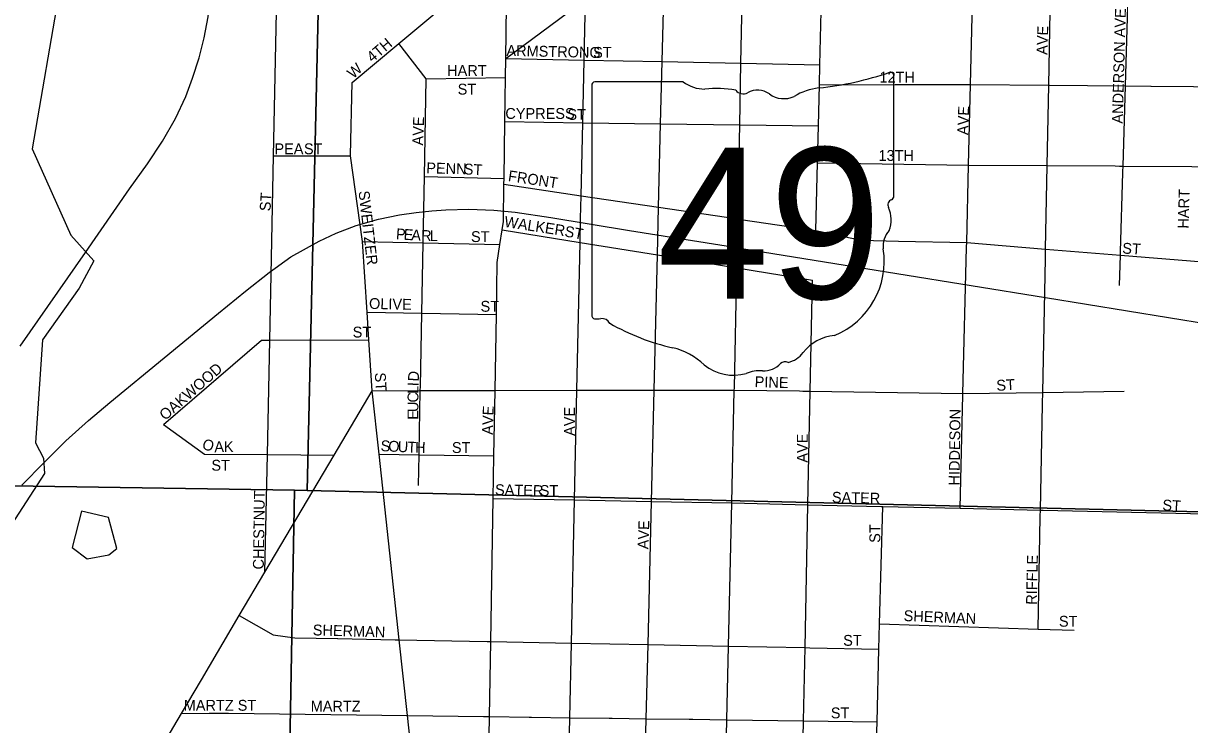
# Model space of a CAD drawing. Extents: x -784 to 1375, y -225 to 440.
# Drawn here: x 287.9 to 308.9, y 339.88 to 352.51 of the extents above; entities that cross this region are included whole.
import ezdxf

# ---------------------------------------------------------------- set-up
doc = ezdxf.new("R2010")
doc.units = 0
for name, color, linetype in [('GM_X_City_Street', 7, 'Continuous'), ('GM_X_City_Street_Text', 7, 'Continuous'), ('GM_X_Minor_Lake', 7, 'Continuous'), ('GM_X_Minor_River', 7, 'Continuous'), ('GM_X_Rail_Line', 7, 'Continuous'), ('GM_X_Section', 7, 'Continuous'), ('GM_X_State_Location', 7, 'Continuous'), ('GM_X_State_Route', 7, 'Continuous'), ('GM_X_State_Shield', 7, 'Continuous'), ('GM_X_Township_Subdivision', 7, 'Continuous'), ('GM_X_Township_Subdivision_Text', 7, 'Continuous')]:
    doc.layers.add(name, color=color, linetype=linetype)

msp = doc.modelspace()

# ---------------------------------------------------------------- linework, layer by layer
at = {"layer": 'GM_X_City_Street'}
for points in [[(293.82, 351.442), (294.658, 352.146), (295.198, 352.598), (296.496, 353.687), (296.611, 353.783), (297.844, 354.818), (299.354, 356.01)], [(296.585, 351.875), (298.02, 352.944), (298.138, 353.027), (298.835, 353.583), (299.456, 354.078), (300.303, 354.834)], [(292.36, 347.981), (292.36, 347.982), (292.404, 350.122), (292.463, 353.002), (292.49, 354.328)], [(298.958, 333.384), (298.958, 333.385), (298.963, 333.583), (299.009, 335.502), (299.057, 337.477), (299.117, 339.989), (299.149, 341.322), (299.211, 343.901), (299.26, 345.904), (299.318, 348.338), (299.339, 349.198), (299.375, 350.7), (299.402, 351.82), (299.43, 352.976), (299.456, 354.078)], [(302.172, 348.778), (302.201, 349.994), (302.217, 350.66), (302.235, 351.404), (302.244, 351.764), (302.273, 352.97), (302.3, 354.083)], [(304.886, 348.487), (304.887, 348.56), (304.922, 349.957), (304.958, 351.406), (304.994, 352.879), (305.035, 354.013)], [(307.7, 349.84), (307.703, 349.939), (307.745, 351.382), (307.788, 352.818), (307.797, 353.948)], [(296.184, 333.611), (296.218, 335.587), (296.251, 337.52), (296.294, 340.026), (296.317, 341.377), (296.361, 343.955), (296.374, 344.723), (296.394, 345.899), (296.418, 347.269), (296.434, 348.201), (296.482, 348.524), (296.522, 348.791), (296.545, 348.943), (296.554, 349.611), (296.556, 349.714), (296.569, 350.739), (296.58, 351.531), (296.585, 351.875), (296.611, 353.783)], [(297.934, 348.991), (297.934, 348.992), (297.943, 349.405), (297.972, 350.719), (297.996, 351.848), (298.02, 352.944)], [(306.305, 348.315), (306.307, 348.444), (306.337, 349.948), (306.365, 351.394), (306.391, 352.724), (306.392, 352.79)], [(295.048, 345.971), (295.074, 347.293), (295.098, 348.554), (295.121, 349.749), (295.155, 351.512), (294.658, 352.146)], [(296.585, 351.875), (297.996, 351.848), (299.402, 351.82), (300.822, 351.792), (302.244, 351.764)], [(294.182, 345.894), (294.122, 346.812), (294.09, 347.31), (294.007, 348.578), (293.792, 350.121), (293.79, 350.135), (293.82, 351.442)], [(295.155, 351.512), (296.58, 351.531)], [(302.235, 351.404), (303.597, 351.405), (303.597, 351.405)], [(303.597, 351.405), (304.958, 351.406), (306.365, 351.394), (306.379, 351.394)], [(306.379, 351.394), (306.38, 351.394), (307.745, 351.382), (308.205, 351.378)], [(308.205, 351.378), (308.208, 351.378), (308.973, 351.371), (310.245, 351.361), (311.377, 351.351), (312.666, 351.296), (314.089, 351.235)], [(296.569, 350.739), (297.972, 350.719), (299.375, 350.7), (300.799, 350.68), (302.217, 350.66)], [(292.404, 350.122), (293.792, 350.121)], [(302.201, 349.994), (304.922, 349.957), (306.337, 349.948), (307.56, 349.94), (307.637, 349.939)], [(307.637, 349.939), (307.703, 349.939), (308.94, 349.93), (309.994, 349.923), (310.144, 349.922)], [(295.121, 349.749), (296.556, 349.714)], [(307.658, 348.402), (307.699, 349.815), (307.7, 349.84)], [(296.554, 349.611), (297.943, 349.405), (299.339, 349.198), (300.764, 348.987), (300.813, 348.98), (300.817, 348.979)], [(297.642, 335.469), (297.642, 335.469), (297.643, 335.543), (297.685, 337.498), (297.74, 340.007), (297.769, 341.349), (297.825, 343.927), (297.867, 345.901), (297.925, 348.564), (297.934, 348.991)], [(300.817, 348.979), (302.172, 348.778), (302.987, 348.605), (303.657, 348.589)], [(296.522, 348.791), (297.925, 348.564), (299.318, 348.338), (300.747, 348.107), (302.111, 347.886)], [(294.007, 348.578), (295.098, 348.554), (296.482, 348.524)], [(303.657, 348.589), (303.661, 348.589), (304.887, 348.56), (306.307, 348.444), (307.656, 348.334), (310.176, 348.128)], [(304.82, 345.826), (304.82, 345.844), (304.885, 348.475), (304.886, 348.487)], [(306.253, 345.671), (306.256, 345.863), (306.304, 348.276), (306.305, 348.315)], [(307.64, 347.786), (307.656, 348.334), (307.658, 348.395), (307.658, 348.402)], [(292.25, 342.626), (292.294, 344.743), (292.336, 346.805), (292.36, 347.981)], [(301.951, 339.952), (301.977, 341.268), (302.029, 343.842), (302.071, 345.886), (302.111, 347.886)], [(294.09, 347.31), (295.074, 347.293), (296.418, 347.269)], [(290.42, 345.287), (292.187, 346.805), (292.289, 346.805), (292.294, 346.805)], [(292.294, 346.805), (292.336, 346.805), (294.122, 346.812)], [(295.025, 344.781), (295.047, 345.896), (295.048, 345.968), (295.048, 345.971)], [(300.513, 337.455), (300.511, 337.455), (300.568, 339.97), (300.598, 341.295), (300.656, 343.874), (300.702, 345.906)], [(300.702, 345.906), (301.875, 345.889)], [(301.875, 345.889), (301.937, 345.888), (302.071, 345.886), (304.82, 345.844), (306.256, 345.863), (307.721, 345.883)], [(304.769, 343.779), (304.82, 345.821), (304.82, 345.826)], [(306.213, 343.637), (306.215, 343.746), (306.252, 345.647), (306.253, 345.671)], [(290.42, 345.287), (291.159, 344.752), (292.294, 344.743), (293.496, 344.734)], [(294.306, 344.752), (295.025, 344.741), (296.374, 344.723)], [(295.014, 344.186), (295.025, 344.741), (295.025, 344.78), (295.025, 344.781)], [(296.361, 343.955), (297.825, 343.927), (299.211, 343.901), (300.656, 343.874)], [(300.656, 343.874), (302.029, 343.842), (303.347, 343.812), (303.376, 343.811)], [(303.205, 337.423), (303.222, 338.027), (303.263, 339.582), (303.272, 339.934), (303.307, 341.242), (303.319, 341.697), (303.376, 343.811)], [(303.376, 343.811), (304.769, 343.779), (306.215, 343.746), (306.245, 343.746), (306.266, 343.745)], [(306.173, 341.603), (306.212, 343.625), (306.213, 343.637)], [(306.266, 343.745), (309.982, 343.66)], [(291.788, 341.844), (292.396, 341.501), (292.786, 341.445), (293.554, 341.43), (293.561, 341.43)], [(303.319, 341.697), (306.173, 341.603), (306.822, 341.582)], [(293.561, 341.43), (294.592, 341.41), (294.598, 341.41)], [(294.598, 341.41), (294.668, 341.409), (296.252, 341.378), (296.257, 341.378)], [(296.257, 341.378), (296.317, 341.377), (297.769, 341.349), (299.149, 341.322), (300.598, 341.295), (301.977, 341.268), (302.062, 341.266), (302.063, 341.266)], [(302.063, 341.266), (303.307, 341.242)], [(291.244, 340.086), (291.596, 340.088), (294.816, 340.046), (296.186, 340.028)], [(296.186, 340.028), (296.221, 340.027), (296.294, 340.026), (297.009, 340.017)], [(297.009, 340.017), (297.05, 340.016), (297.74, 340.007), (298.451, 339.998)], [(298.451, 339.998), (298.502, 339.997), (299.117, 339.989), (299.892, 339.979)], [(299.892, 339.979), (299.954, 339.978), (300.568, 339.97), (301.951, 339.952), (303.272, 339.934)], [(301.926, 338.713), (301.951, 339.952)]]:
    msp.add_lwpolyline(points, dxfattribs=at)
at = {"layer": 'GM_X_Minor_Lake'}
for points in [[(289.432, 343.613), (288.948, 343.728), (288.776, 343.072), (289.048, 342.865)], [(289.048, 342.865), (289.44, 342.938), (289.582, 343.054), (289.432, 343.613)]]:
    msp.add_lwpolyline(points, dxfattribs=at)
at = {"layer": 'GM_X_Minor_River'}
msp.add_lwpolyline([(288.558, 353.149), (288.058, 350.249), (288.753, 348.693), (289.169, 348.231), (288.902, 347.742), (288.243, 346.812), (288.118, 344.955), (288.262, 344.678), (288.281, 344.403), (286.703, 341.975), (278.796, 325.615), (278.65, 325.382)], dxfattribs=at)
at = {"layer": 'GM_X_Rail_Line'}
for points in [[(287.84, 346.697), (289.019, 348.383), (289.811, 349.528), (290.134, 349.979), (290.402, 350.384), (290.641, 350.797), (290.824, 351.192), (290.947, 351.52), (291.066, 351.89), (291.156, 352.248), (291.228, 352.627), (291.292, 353.244), (291.33, 353.78), (291.356, 354.283), (291.339, 354.87), (291.22, 356.73), (291.169, 357.471), (291.071, 359.05), (291.003, 360.284), (290.936, 360.877), (290.873, 362.102), (290.876, 363.223)], [(287.87, 344.193), (288.275, 344.604), (288.662, 344.991), (289.073, 345.356), (289.456, 345.682), (291.413, 347.289), (291.9, 347.688), (292.326, 348.022), (292.713, 348.306), (293.227, 348.586), (293.53, 348.728), (293.891, 348.87), (294.294, 348.981), (294.67, 349.061), (294.973, 349.104), (295.253, 349.134), (295.506, 349.153), (295.92, 349.161), (296.369, 349.146), (296.753, 349.107), (297.397, 349.012), (298.817, 348.781), (300.82, 348.458)], [(300.82, 348.458), (300.839, 348.455)], [(300.839, 348.455), (302.143, 348.244), (303.626, 348.002)], [(303.626, 348.002), (306.309, 347.573), (311.473, 346.733), (313.943, 346.334), (317.442, 345.777), (321.968, 345.028), (324.501, 344.623), (326.856, 344.239), (328.997, 343.894), (333.611, 343.138)]]:
    msp.add_lwpolyline(points, dxfattribs=at)
at = {"layer": 'GM_X_Section'}
for points in [[(272.601, 365.183), (293.485, 364.699), (293.008, 344.097), (292.781, 344.102), (272.386, 344.418)], [(293.485, 364.699), (314.451, 364.338), (313.882, 343.598), (293.008, 344.097)], [(272.386, 344.418), (292.781, 344.102), (292.404, 323.388), (271.521, 323.911), (271.941, 344.413)], [(293.008, 344.097), (313.882, 343.598), (313.315, 322.896), (292.404, 323.388), (292.781, 344.102)]]:
    msp.add_lwpolyline(points, close=True, dxfattribs=at)
at = {"layer": 'GM_X_State_Route'}
for points in [[(300.753, 348.399), (300.753, 348.403), (300.764, 348.987), (300.799, 350.68), (300.822, 351.792), (300.844, 352.905)], [(300.703, 345.942), (300.703, 345.947), (300.747, 348.107), (300.753, 348.399)], [(292.25, 342.626), (293.496, 344.734), (294.182, 345.894)], [(294.182, 345.894), (295.047, 345.896), (296.394, 345.899), (297.867, 345.901), (299.26, 345.904), (300.702, 345.906), (300.703, 345.942)], [(295.047, 337.912), (295.003, 338.324), (294.816, 340.046), (294.668, 341.409), (294.306, 344.752), (294.182, 345.894)], [(291.106, 340.689), (291.106, 340.69), (291.788, 341.844), (292.25, 342.626)], [(289.337, 337.695), (289.337, 337.697), (289.539, 338.038), (290.748, 340.083), (291.106, 340.689)]]:
    msp.add_lwpolyline(points, dxfattribs=at)
at = {"layer": 'GM_X_State_Shield'}
for p, q in [((299.782, 351.457), (298.19, 351.457)), ((303.574, 349.4), (303.574, 351.559)), ((298.136, 351.386), (298.136, 347.258)), ((303.574, 349.401), (303.574, 349.4))]:
    msp.add_line(p, q, dxfattribs=at)
for centre, radius, start, end in [((301.637, 357.084), 5.767, 275.8445, 288.9065), ((303.514, 351.568), 0.0605, 351.8621, 97.738), ((298.198, 351.395), 0.063, 98.1301, 188.1301), ((300.161, 351.936), 0.611, 231.6195, 271.1119), ((300.364, 349.14), 2.194, 80.4867, 94.9883), ((300.862, 351.416), 0.176, 219.7921, 297.1024), ((301.121, 350.939), 0.367, 54.4667, 119.1411), ((301.594, 351.593), 0.441, 233.8562, 294.8282), ((302.373, 350.196), 1.16, 97.3462, 120.7689), ((303.56, 349.242), 0.0937, 107.944, 210.337), ((303.51, 349.392), 0.0648, 289.6038, 7.7341), ((302.964, 348.969), 0.562, 340.033, 23.6496), ((303.791, 348.497), 0.409, 136.8065, 186.9296), ((301.96, 348.222), 1.442, 292.3089, 8.9858), ((298.199, 347.249), 0.0636, 171.9584, 258.3066), ((298.209, 347.672), 0.485, 267.339, 280.6039), ((298.308, 347.02), 0.175, 29.7484, 93.2717), ((300.516, 350.729), 4.165, 240.4129, 257.1985), ((302.568, 346.1), 0.79, 94.4031, 142.5768), ((299.274, 345.404), 1.303, 47.1842, 75.836), ((301.567, 346.858), 0.466, 282.8732, 323.2771), ((301.222, 346.691), 0.441, 268.777, 315.5493), ((301.62, 346.291), 0.124, 65.7517, 132.6484), ((300.684, 347), 0.827, 230.7004, 286.2918), ((301.161, 345.573), 0.679, 85.6951, 111.2099)]:
    msp.add_arc(centre, radius, start, end, dxfattribs=at)
at = {"layer": 'GM_X_Township_Subdivision'}
msp.add_lwpolyline([(290.748, 340.083), (291.596, 340.088)], dxfattribs=at)

# ---------------------------------------------------------------- texts
at = {"layer": 'GM_X_City_Street_Text'}
for s, height, rotation, p in [('ANDERSON AVE', 0.19531, 88.4087, (307.697, 350.701)), ('4TH', 0.1953, 40.0988, (294.183, 351.794)), ('AVE', 0.1953, 88.0264, (306.339, 351.939)), ('ARMSTRONG', 0.1953, 358.6838, (296.597, 351.923)), ('ST', 0.1953, 0, (298.16, 351.888)), ('W', 0.195, 41.983, (293.839, 351.501)), ('HART', 0.1953, 0, (295.531, 351.562)), ('12TH', 0.1953, 0, (303.316, 351.441)), ('ST', 0.1953, 0, (295.72, 351.226)), ('CYPRESS', 0.1953, 0, (296.579, 350.788)), ('AVE', 0.1953, 88.0245, (304.913, 350.495)), ('AVE', 0.1953, 88.0242, (295.098, 350.306)), ('ST', 0.1953, 0, (297.696, 350.771)), ('PEA', 0.1953, 0, (292.42, 350.152)), ('ST', 0.1953, 0, (292.952, 350.152)), ('13TH', 0.1953, 0, (303.299, 350.032)), ('PENN', 0.1953, 358.4097, (295.153, 349.809)), ('ST', 0.1953, 356.4256, (295.825, 349.791)), ('FRONT', 0.1953, 351.3474, (296.619, 349.671)), ('HART', 0.1953, 88.492, (308.883, 348.81)), ('ST', 0.1953, 86.422, (292.348, 349.121)), ('SWEITZER', 0.1953, 276.6125, (293.934, 349.484)), ('WALKER', 0.1953, 351.1808, (296.55, 348.846)), ('P', 0.195, 356.1173, (294.605, 348.623)), ('E', 0.195, 356.0901, (294.742, 348.613)), ('A', 0.195, 356.2686, (294.88, 348.604)), ('R', 0.195, 358.5923, (295.06, 348.592)), ('L', 0.195, 359.939, (295.22, 348.588)), ('ST', 0.1953, 0, (295.96, 348.571)), ('ST', 0.1953, 349.3727, (297.634, 348.674)), ('ST', 0.1953, 356.4256, (307.684, 348.365)), ('OLIVE', 0.1953, 358.6368, (294.122, 347.368)), ('ST', 0.1953, 0, (296.132, 347.316)), ('ST', 0.1953, 0, (293.829, 346.852)), ('OAKWOOD', 0.1953, 41.1121, (290.453, 345.348)), ('ST', 0.1953, 273.5772, (294.227, 346.216)), ('D', 0.195, 86.5123, (295.018, 346.056)), ('PINE', 0.1953, 358.1534, (301.066, 345.959)), ('L', 0.195, 89.3648, (295.013, 345.835)), ('I', 0.195, 87.5413, (295.014, 345.971)), ('ST', 0.1953, 3.5744, (305.428, 345.89)), ('C', 0.195, 89.9703, (295.013, 345.681)), ('U', 0.195, 89.9674, (295.013, 345.509)), ('E', 0.195, 89.9658, (295.012, 345.372)), ('AVE', 0.1953, 88.0242, (296.353, 345.098)), ('AVE', 0.1953, 90, (297.831, 345.08)), ('HIDDESON', 0.1953, 89.1935, (304.758, 344.186)), ('AVE', 0.1953, 90, (302.025, 344.598)), ('O', 0.195, 339.8974, (291.101, 344.858)), ('A', 0.195, 1.142, (291.34, 344.786)), ('K', 0.195, 0, (291.51, 344.79)), ('S', 0.195, 357.2669, (294.329, 344.807)), ('O', 0.195, 357.2878, (294.467, 344.8)), ('U', 0.195, 357.2669, (294.638, 344.792)), ('T', 0.195, 357.289, (294.81, 344.784)), ('H', 0.195, 358.4446, (294.952, 344.778)), ('ST', 0.1953, 0, (295.616, 344.773)), ('ST', 0.1953, 0, (291.285, 344.454)), ('CHESTNUT', 0.1953, 89.2156, (292.228, 342.674)), ('SATER', 0.1953, 358.6988, (296.391, 344.016)), ('ST', 0.1953, 0, (297.198, 343.999)), ('SATER', 0.1953, 358.6988, (302.458, 343.879)), ('ST', 0.1953, 356.412, (308.406, 343.741)), ('AVE', 0.1953, 88.0242, (299.155, 343.036)), ('ST', 0.1953, 90, (303.331, 343.155)), ('RIFFLE', 0.1953, 88.7541, (306.15, 342.038)), ('SHERMAN', 0.1953, 357.4721, (303.748, 341.748)), ('ST', 0.1953, 0, (306.548, 341.645)), ('SHERMAN', 0.1953, 358.3144, (293.109, 341.49)), ('ST', 0.1953, 0, (302.663, 341.301)), ('MARTZ', 0.1953, 0, (293.073, 340.115)), ('ST', 0.1953, 0, (302.44, 339.995))]:
    msp.add_text(s, height=height, rotation=rotation, dxfattribs=at).set_placement(p)
at = {"layer": 'GM_X_State_Location'}
for s in ['s', 'r']:
    msp.add_text(s, height=0.00391, dxfattribs=at).set_placement((300.794, 349.048))
msp.add_text('49', height=0.00391, rotation=0, dxfattribs=at).set_placement((299.81, 348.764))
at = {"layer": 'GM_X_State_Shield'}
msp.add_text('49', height=2.7191, dxfattribs=at).set_placement((299.309, 347.55))
at = {"layer": 'GM_X_Township_Subdivision_Text'}
msp.add_text('MARTZ ST', height=0.1953, rotation=0, dxfattribs=at).set_placement((290.787, 340.132))

doc.saveas('drawing.dxf')
